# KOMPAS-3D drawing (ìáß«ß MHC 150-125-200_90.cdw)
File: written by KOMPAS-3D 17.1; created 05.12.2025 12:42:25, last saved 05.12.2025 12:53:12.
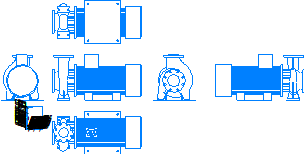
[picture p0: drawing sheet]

Sheet 1: A4, portrait

Title block, sheet 1: name: Насос MHC 150-125-200_90 / 90 кВт 3х380В; material: Сталь 10  ГОСТ 1050-88; mass: 842,83; sheets: 1; sheet format: A4; stored path: \\adlc.lan\data\АДЛ_ПКД\3D-модели\ADL production\Насосы ГРАНПАМП\Насосы ГРАНПАМП серии МНС\KOMPAS 3D\Насос MHC 150-125-200_90.cdw

Views: Вид 1, Спереди, Проекционный вид 2, Проекционный вид 3, Проекционный вид 4, Проекционный вид 5, Проекционный вид 6
Referenced files in \\adlc.lan\data\АДЛ_ПКД\3D-модели\ADL production\Насосы ГРАНПАМП\Насосы ГРАНПАМП серии МНС\KOMPAS 3D\: Насос MHC 150-125-200_90.m3d
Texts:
  Andrey
  АДЛ
Dimensions and other numbers on the sheet: 1:1; 1; 90 кВт 3х380В; 842,83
